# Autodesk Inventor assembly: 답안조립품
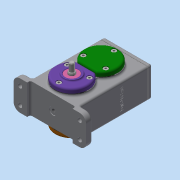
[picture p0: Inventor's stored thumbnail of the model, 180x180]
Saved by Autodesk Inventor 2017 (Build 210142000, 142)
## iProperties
Part Number: 답안조립품
Material: 일반
Document SubType Name: Assembly
Designer: mrc
Mass: 1460.95 g
Surface Area: 1575.48 cm^2
Volume: 385.032 cm^3
Density: 3.79437 g/cm^3
Author: mrc
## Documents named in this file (24)
- C:\Users\mrc\Desktop\600506V1022\답안조립품.iam
- C:\Users\mrc\Desktop\600506V1022\본체.ipt
- C:\Users\mrc\Desktop\600506V1022\개스킷 A.ipt
- C:\Users\mrc\Desktop\600506V1022\개스킷 B.ipt
- C:\Users\mrc\Desktop\600506V1022\개스킷 C.ipt
- C:\Users\mrc\Desktop\600506V1022\베어링 6001.ipt
- 베어링 6001.ipt
- C:\Users\mrc\Desktop\600506V1022\베어링 6002.ipt
- 베어링 6002.ipt
- C:\Users\mrc\Desktop\600506V1022\볼트 M4.ipt
- C:\Users\mrc\Desktop\600506V1022\스퍼기어 A.ipt
- C:\Users\mrc\Desktop\600506V1022\스퍼기어 B.ipt
- C:\Users\mrc\Desktop\600506V1022\오일 실 10 20 7.ipt
- C:\Users\mrc\Desktop\600506V1022\오일 실 12 22 7.ipt
- C:\Users\mrc\Desktop\600506V1022\축 A.ipt
- C:\Users\mrc\Desktop\600506V1022\축 B.ipt
- C:\Users\mrc\Desktop\600506V1022\칼라.ipt
- C:\Users\mrc\Desktop\600506V1022\커버 A.ipt
- C:\Users\mrc\Desktop\600506V1022\커버 B.ipt
- C:\Users\mrc\Desktop\600506V1022\커버 C.ipt
- C:\Users\mrc\Desktop\600506V1022\커버 D.ipt
- C:\Users\mrc\Desktop\600506V1022\커버 E.ipt
- C:\Users\mrc\Desktop\600506V1022\키 4 x 4 x 12.ipt
- C:\Users\mrc\Desktop\600506V1022\키 5 x 5 x 12.ipt
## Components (5 placed, 3 different names)
1. 개스킷 A:1
2. 개스킷 B:1
3. 개스킷 C:1
4. 개스킷 B:2
5. 개스킷 B:3
